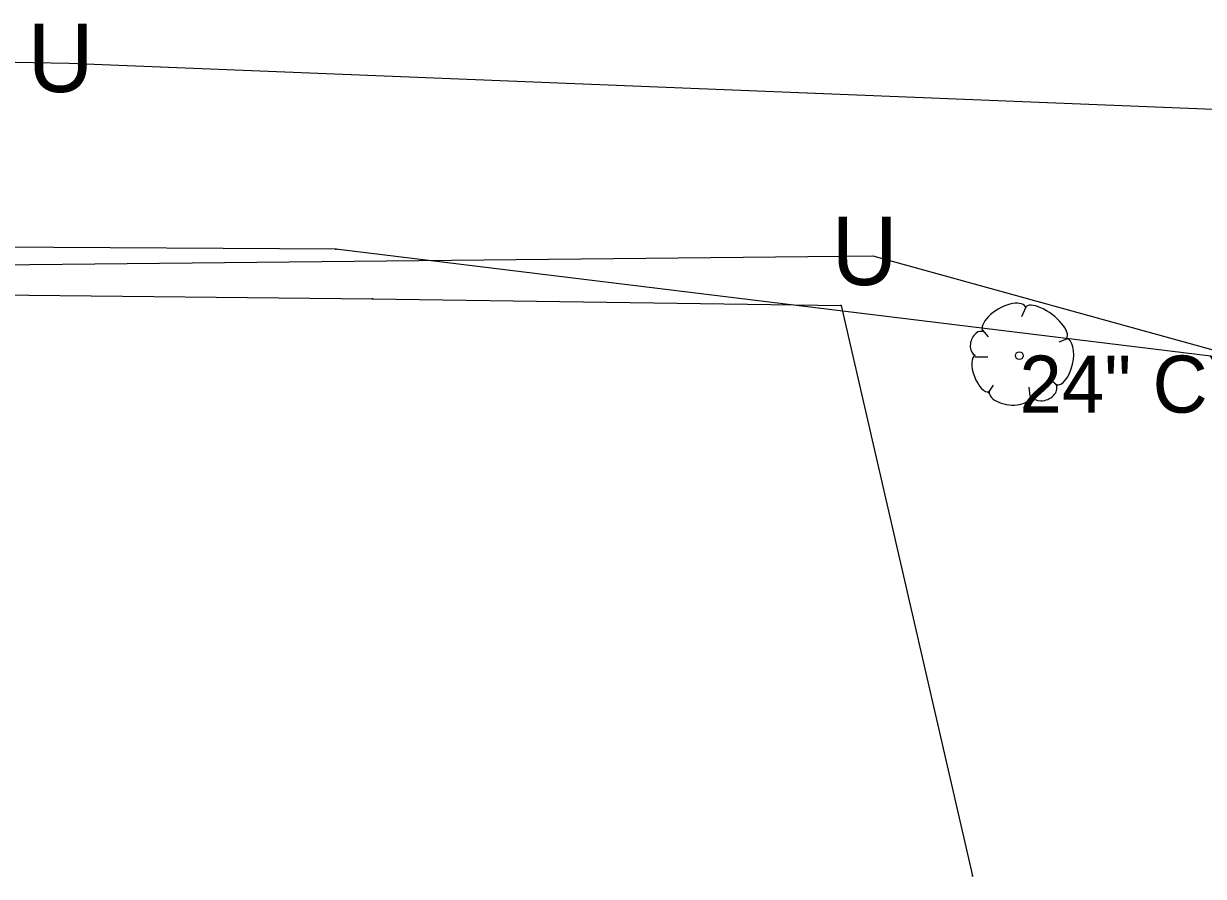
# Model space of a CAD drawing. Extents: x 1930288 to 1941089, y 588389 to 611475.
# Drawn here: x 1930488 to 1930591.3, y 598060.1 to 598134.8 of the extents above; entities that cross this region are included whole.
import ezdxf

# ---------------------------------------------------------------- set-up
doc = ezdxf.new("R2010")
doc.units = 0
for name, color, linetype in [('Default', 7, 'Continuous'), ('S_FENCE', 7, 'Continuous'), ('S_GAS_UTILITIES', 7, 'Continuous'), ('S_MSC_PT_SYM', 7, 'Continuous'), ('S_TREE', 7, 'Continuous'), ('S_TREE_ANNOT', 7, 'Continuous'), ('S_UNDERGROUND_CABLE', 7, 'Continuous'), ('S_UTL_PT_SYM', 7, 'Continuous')]:
    doc.layers.add(name, color=color, linetype=linetype)

msp = doc.modelspace()

# ---------------------------------------------------------------- linework, layer by layer
at = {"layer": 'S_FENCE'}
for p, q in [((1930432.64, 598111.64), (1930518.54, 598110.72)), ((1930518.54, 598110.72), (1930559.6, 598110.12)), ((1930559.6, 598110.12), (1930571.12, 598060.14))]:
    msp.add_line(p, q, dxfattribs=at)
at = {"layer": 'S_GAS_UTILITIES'}
for p, q in [((1930515.32, 598115.07), (1930457.65, 598115.39)), ((1930639.47, 598099.89), (1930515.32, 598115.07))]:
    msp.add_line(p, q, dxfattribs=at)
at = {"layer": 'S_MSC_PT_SYM'}
for points in [[(1930518.54, 598110.72), (1930518.54, 598110.77), (1930518.54, 598110.72), (1930518.49, 598110.72), (1930518.54, 598110.72), (1930518.54, 598110.67), (1930518.54, 598110.72), (1930518.59, 598110.72)], [(1930559.6, 598110.12), (1930559.6, 598110.17), (1930559.6, 598110.12), (1930559.55, 598110.12), (1930559.6, 598110.12), (1930559.6, 598110.07), (1930559.6, 598110.12), (1930559.65, 598110.12)], [(1930571.12, 598060.14), (1930571.12, 598060.19), (1930571.12, 598060.14), (1930571.07, 598060.14), (1930571.12, 598060.14), (1930571.12, 598060.09), (1930571.12, 598060.14), (1930571.17, 598060.14)]]:
    msp.add_lwpolyline(points, dxfattribs=at)
at = {"layer": 'S_TREE'}
for p, q in [((1930575.78, 598109.98), (1930575.39, 598109.13)), ((1930571.98, 598107.97), (1930572.48, 598107.38)), ((1930579.34, 598107.19), (1930578.68, 598106.92)), ((1930571.32, 598105.64), (1930572.44, 598105.64)), ((1930572.48, 598102.46), (1930572.95, 598103.16)), ((1930576.16, 598102.19), (1930576.09, 598102.97)), ((1930578.57, 598103.08), (1930578.1, 598103.51))]:
    msp.add_line(p, q, dxfattribs=at)
msp.add_circle((1930575.22, 598105.74), 0.341, dxfattribs=at)
for centre, major_axis, ratio, start_param, end_param in [((1930573.88, 598108.94), (1.86, 1.08), 0.471018, 0, 3.141593), ((1930577.54, 598108.61), (-1.81, 1.36), 0.405113, 3.141593, 6.283186), ((1930571.65, 598106.82), (0.31, 1.03), 0.646762, 0, 3.141593), ((1930578.89, 598105.21), (0.46, 2.04), 0.482994, 3.141593, 6.283185), ((1930571.95, 598104.17), (-0.61, 1.6), 0.420543, 6.283185, 9.424777), ((1930577.37, 598102.68), (1.09, 0.46), 0.711534, 3.141592, 6.283185), ((1930574.41, 598102.39), (-1.83, 0.19), 0.529943, 0, 3.141593)]:
    msp.add_ellipse(centre, major_axis=major_axis, ratio=ratio, start_param=start_param, end_param=end_param, dxfattribs=at)
at = {"layer": 'S_UNDERGROUND_CABLE'}
for p, q in [((1930389.07, 598132.91), (1930491.94, 598131.38)), ((1930491.94, 598131.38), (1930623.81, 598126.06)), ((1930485.45, 598113.69), (1930562.39, 598114.47)), ((1930562.39, 598114.47), (1930635.06, 598094.39))]:
    msp.add_line(p, q, dxfattribs=at)
at = {"layer": 'S_UTL_PT_SYM'}
msp.add_lwpolyline([(1930515.32, 598115.07), (1930515.32, 598115.12), (1930515.32, 598115.07), (1930515.27, 598115.07), (1930515.32, 598115.07), (1930515.32, 598115.02), (1930515.32, 598115.07), (1930515.37, 598115.07)], dxfattribs=at)

# ---------------------------------------------------------------- texts
at = {"layer": 'Default'}
for p in [(1930488.31, 598128.84), (1930558.76, 598111.92)]:
    msp.add_text('U', height=6, rotation=360, dxfattribs=at).set_placement(p)
at = {"layer": 'S_TREE_ANNOT'}
msp.add_text('24" CYPRESS', height=5, dxfattribs=at).set_placement((1930575.22, 598100.74))

doc.saveas('drawing.dxf')
